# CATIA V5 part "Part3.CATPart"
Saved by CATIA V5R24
Part number: Link2-2
Bounding box of the stored display mesh (mm): x -20 to 1, y -90 to 0, z -15 to 95
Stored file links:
  G:\_CAD수업\DMU_paradoxes\2\Part3.CATPart
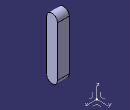
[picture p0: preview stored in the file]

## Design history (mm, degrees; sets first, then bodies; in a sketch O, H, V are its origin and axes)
AxisSystem1: origin (0, 0, 0), X (1, 0, 0), Y (0, 1, 0), Z (0, 0, 1)
Body1 (main body)
  Sketch1 on YZ plane of AxisSystem1, origin (0, 0, 0), H (0, 1, 0), V (0, 0, 1)
    line L1 (-90, 95) -> (-70, 95)
    line L2 (-70, 95) -> (-70, -15)
    line L3 (-70, -15) -> (-90, -15)
    line L4 (-90, -15) -> (-90, 95)
    horizontal: L1 H, L3 H
    vertical: L2 V, L4 V
  Pad1: profile Sketch1, direction (-1, 0, 0), length 20, opposite side length 1
  TritangentFillet1: Face1 face of Pad1 from Sketch1.L4, Face2 face of Pad1 from Sketch1.L2, RemoveFace face of Pad1 from Sketch1.L3
  TritangentFillet2: Face1 face of Pad1 from Sketch1.L4, Face2 face of Pad1 from Sketch1.L2, RemoveFace face of Pad1 from Sketch1.L1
